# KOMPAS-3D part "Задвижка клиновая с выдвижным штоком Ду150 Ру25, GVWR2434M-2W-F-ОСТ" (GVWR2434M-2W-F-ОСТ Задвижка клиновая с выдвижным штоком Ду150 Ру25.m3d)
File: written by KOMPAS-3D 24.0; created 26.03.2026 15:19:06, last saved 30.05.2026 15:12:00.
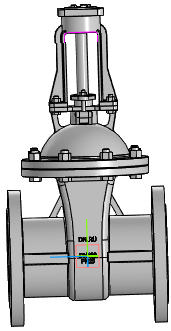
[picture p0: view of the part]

Document properties: Автор: R2D2; Полное имя файла: E:\Работа\Зайцев\GVWR2434M-2W-F-ОСТ Задвижка клиновая с выдвижным штоком DN.ru Ду50-300 Ру25\исходные материалы\DN150\GVWR2434M-2W-F-ОСТ Задвижка клиновая с выдвижным штоком Ду150 Ру25.m3d

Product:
- Component [detail]: ANSI B18.2.4.2M - M16x2 - 24  | designation ANSI B18.2.4.2M - M16x2  | qty 8  | pos. 2  | Комментарий: Типы метрических   шестигранных гаек   2; Автор: R2D2; additional columns: Сталь, мягкая; source file: ANSI B18.2.4.2M - M16x2 ANSI B18.2.4.2M - M16x2 - 24.m3d
- Component [detail]: AS 1110 - M16 x 60  | qty 8  | pos. 3  | Комментарий: Болты и винты   шестигранные точные   метрические ISO; Автор: R2D2; additional columns: Сталь, мягкая; source file: AS 1110 - M16 x 60 AS 1110 - M16 x 60.m3d
- Component [detail]: AS 1110 - M10 x 35  | qty 4  | pos. 4  | Комментарий: Болты и винты   шестигранные точные   метрические ISO; Автор: R2D2; additional columns: Сталь, мягкая; source file: AS 1110 - M10 x 35 AS 1110 - M10 x 35.m3d
- Component [detail]: ANSI B18.2.4.2M - M10x1,5 - 16  | designation ANSI B18.2.4.2M - M10x1,5  | qty 4  | pos. 5  | Комментарий: Типы метрических   шестигранных гаек   2; Автор: R2D2; additional columns: Сталь, мягкая; source file: ANSI B18.2.4.2M - M10x1,5 ANSI B18.2.4.2M - M10x1,5 - 16.m3d
- Component [detail]: ANSI B18.2.4.2M - M8x1,25 - 13  | designation ANSI B18.2.4.2M - M8x1,25  | qty 1  | pos. 6  | Комментарий: Типы метрических   шестигранных гаек   2; Автор: R2D2; additional columns: Сталь, мягкая; source file: ANSI B18.2.4.2M - M8x1,25 ANSI B18.2.4.2M - M8x1,25 - 13.m3d
- Component [detail]: Деталь1  | qty 1  | pos. 7  | Автор: R2D2; additional columns: Типовые; source file: 2.m3d
- Component [detail]: Фланец  | qty 1  | pos. 8  | Автор: R2D2; additional columns: Типовые; source file: Фланец DN150 PN25 b30.m3d
- Component [detail]: Фланец  | qty 1  | pos. 9  | Автор: R2D2; additional columns: Типовые; source file: Фланец DN150 PN25 b30.m3d
- Component [detail]: ANSI B18.2.4.2M - M8x1,25 - 13  | designation ANSI B18.2.4.2M - M8x1,25-01  | qty 1  | pos. 6  | Комментарий: Типы метрических   шестигранных гаек   2; Автор: R2D2; additional columns: Сталь, мягкая; source file: ANSI B18.2.4.2M - M8x1,25 ANSI B18.2.4.2M - M8x1,25 - 13.m3d
- Component [assembly]: DN50_3D_STEP  | designation Сборка  | qty 1  | Масса: 2.725126; Автор: R2D2; source file: Фланец А.a3d
- Part/product: Задвижка клиновая с выдвижным штоком Ду150 Ру25  | designation GVWR2434M-2W-F-ОСТ
    Масса: 60
    Раздел спецификации: Прочие изделия
    Примечание: D040-07589
    additional columns: D040-10013

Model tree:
1. Массив по сетке:2  (labels: Грань.Твердое тело1; Вершина.Твердое тело1)  (4 pattern instances)
     Шаг 1 = 50; Угол раствора = 90; Шаг 2 = 120
2. Массив по концентрической сетке:1  (labels: Грань.Твердое тело1)  (8 pattern instances)
     Шаг 2 = 360
3. Элемент выдавливания:1  (with: Грань.Элемент выдавливания:2, Грань.Элемент вращения:1)
     Расстояние 1 = 36.9829
4. Элемент выдавливания:2  (with: Грань.Элемент выдавливания:1, Грань.Элемент вращения:1)
     Расстояние 1 = 38.9519
5. Скругление:1  (with: Ребро.Элемент выдавливания:2, Ребро.Элемент выдавливания:1)
     Радиус = 3
6. Элемент выдавливания:3  (with: Грань.Элемент выдавливания:1)
     Расстояние 1 = 60
7. Эскиз:1  (with: Вершина.Элемент выдавливания:3, Ребро.Операция без истории:2)
8. Элемент по траектории:1  (with: Грань.Элемент выдавливания:3)
     Длина траектории = 112.527
9. Элемент выдавливания:4  (with: Грань.Элемент выдавливания:1, Грань.Элемент по траектории:1)
     Расстояние 1 = 134.696
10. Эскиз:2
11. Элемент выдавливания:5  (with: Грань.Элемент выдавливания:1, Грань.Элемент вращения:1, Грань.Операция без истории:2)  (labels: Грань.Твердое тело1; Грань.Solid1; Solid1; Твердое тело1)
     Расстояние 1 = 98.5; Смещение 1 = 1; Расстояние = -175; Ориентация = 2; Ориентация = 2; Расстояние = -550

Referenced files in E:\Работа\Зайцев\GVWR2434M-2W-F-ОСТ Задвижка клиновая с выдвижным штоком DN.ru Ду50-300 Ру25\исходные материалы\DN150\: ANSI B18.2.4.2M - M16x2 ANSI B18.2.4.2M - M16x2 - 24.m3d, AS 1110 - M16 x 60 AS 1110 - M16 x 60.m3d, AS 1110 - M10 x 35 AS 1110 - M10 x 35.m3d, ANSI B18.2.4.2M - M10x1,5 ANSI B18.2.4.2M - M10x1,5 - 16.m3d, ANSI B18.2.4.2M - M8x1,25 ANSI B18.2.4.2M - M8x1,25 - 13.m3d, 2.m3d, Фланец А.a3d, Фланец DN150 PN25 b30.m3d
Referenced files in E:\Работа\Зайцев\GVWR3131M-2W-F-S Задвижка клиновая с выдвижным штоком DN.ru Ду50-200 Ру63\DN150\исходные материалы\: ANSI B18.2.4.2M - M10x1,5 ANSI B18.2.4.2M - M10x1,5 - 16.m3d, AS 1110 - M10 x 35 AS 1110 - M10 x 35.m3d, ANSI B18.2.4.2M - M16x2 ANSI B18.2.4.2M - M16x2 - 24.m3d, AS 1110 - M16 x 60 AS 1110 - M16 x 60.m3d
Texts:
  GVWR2434M-2W-F-ОСТ
  DN150
  GOST 26.020 Pr3
  PN25
  ANSI B18.2.4.2M - M16x2 ANSI B18.2.4.2M - M16x2 - 24 (1)
  AS 1110 - M16 x 60 AS 1110 - M16 x 60 (1)
  AS 1110 - M10 x 35 AS 1110 - M10 x 35 (1)
  ANSI B18.2.4.2M - M10x1,5 ANSI B18.2.4.2M - M10x1,5 - 16 (1)
  ANSI B18.2.4.2M - M8x1,25 ANSI B18.2.4.2M - M8x1,25 - 13
  Деталь1 Деталь1
  Фланец (1)
  Фланец (2)
  ANSI B18.2.4.2M - M10x1,5 ANSI B18.2.4.2M - M10x1,5 - 16 (2)
  AS 1110 - M10 x 35 AS 1110 - M10 x 35 (2)
  ANSI B18.2.4.2M - M10x1,5 ANSI B18.2.4.2M - M10x1,5 - 16 (3)
  AS 1110 - M10 x 35 AS 1110 - M10 x 35 (3)
  ANSI B18.2.4.2M - M10x1,5 ANSI B18.2.4.2M - M10x1,5 - 16 (4)
  AS 1110 - M10 x 35 AS 1110 - M10 x 35 (4)
  ANSI B18.2.4.2M - M16x2 ANSI B18.2.4.2M - M16x2 - 24 (2)
  AS 1110 - M16 x 60 AS 1110 - M16 x 60 (2)
  ANSI B18.2.4.2M - M16x2 ANSI B18.2.4.2M - M16x2 - 24 (3)
  AS 1110 - M16 x 60 AS 1110 - M16 x 60 (3)
  ANSI B18.2.4.2M - M16x2 ANSI B18.2.4.2M - M16x2 - 24 (4)
  AS 1110 - M16 x 60 AS 1110 - M16 x 60 (4)
  ANSI B18.2.4.2M - M16x2 ANSI B18.2.4.2M - M16x2 - 24 (5)
  AS 1110 - M16 x 60 AS 1110 - M16 x 60 (5)
  ANSI B18.2.4.2M - M16x2 ANSI B18.2.4.2M - M16x2 - 24 (6)
  AS 1110 - M16 x 60 AS 1110 - M16 x 60 (6)
  ANSI B18.2.4.2M - M16x2 ANSI B18.2.4.2M - M16x2 - 24 (7)
  AS 1110 - M16 x 60 AS 1110 - M16 x 60 (7)
  ANSI B18.2.4.2M - M16x2 ANSI B18.2.4.2M - M16x2 - 24 (8)
  AS 1110 - M16 x 60 AS 1110 - M16 x 60 (8)
  ANSI B18.2.4.2M - M8x1,25-01 ANSI B18.2.4.2M - M8x1,25 - 13
  Сборка DN50_3D_STEP
  Ось Z.Начало координат
  Ось Y.Начало координат
  Плоскость ZY.Начало координат
  Плоскость ZX.Начало координат
  Плоскость XY.Начало координат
